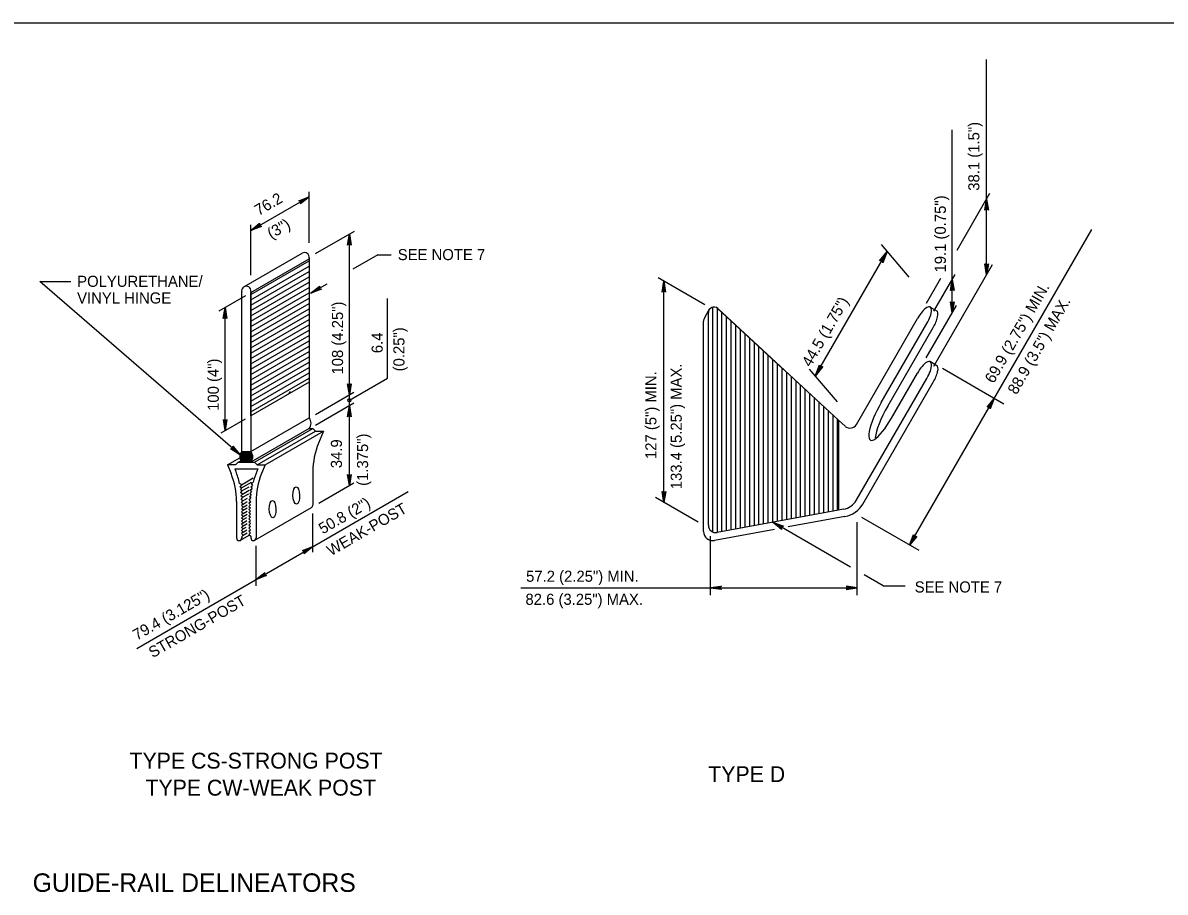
# Model space of a CAD drawing. Extents: x 640253 to 641999, y 298458 to 299646.
# Drawn here: x 640490.1 to 640798.8, y 298801.7 to 299036.6 of the extents above; entities that cross this region are included whole.
import ezdxf

# ---------------------------------------------------------------- set-up
doc = ezdxf.new("R2010")
doc.units = 0
doc.layers.add('1', color=7, linetype='Continuous')
doc.layers.add('2', color=7, linetype='Continuous')

msp = doc.modelspace()

# ---------------------------------------------------------------- linework, layer by layer
at = {"layer": '1'}
msp.add_line((640293.31, 299036.63), (641079.31, 299036.63), dxfattribs=at)
at = {"layer": '2'}
for p, q in [((640750.54, 298968.53), (640750.55, 299026.71)), ((640741.28, 298967.28), (640741.29, 299007.75)), ((640551.76, 298980.53), (640567.51, 298989.62)), ((640567.51, 298977.15), (640567.51, 298990.93)), ((640742.56, 298975.19), (640751.44, 298990.57)), ((640551.76, 298968.46), (640551.76, 298982)), ((640569.19, 298974.27), (640579.72, 298980.35)), ((640578.36, 298936.09), (640578.36, 298979.57)), ((640729.75, 298895.51), (640778.99, 298980.76)), ((640729.66, 298967.89), (640722.11, 298976.71)), ((640549.88, 298965.29), (640565.62, 298974.38)), ((640586.04, 298973.92), (640579.26, 298970.05)), ((640586.04, 298973.92), (640589.7, 298973.92)), ((640704.26, 298941.18), (640723.7, 298974.85)), ((640551.76, 298963.24), (640567.51, 298972.33)), ((640551.76, 298961.8), (640567.51, 298970.89)), ((640567.51, 298973.08), (640567.51, 298929.88)), ((640736.28, 298943.84), (640752.15, 298971.31)), ((640551.76, 298960.36), (640567.51, 298969.44)), ((640551.76, 298958.91), (640567.51, 298968)), ((640674.43, 298960.44), (640661.77, 298967.76)), ((640734.29, 298960.88), (640738.18, 298967.61)), ((640736.31, 298958.67), (640742.03, 298968.58)), ((640741.28, 298958.24), (640741.28, 298967.28)), ((640494.74, 298966.76), (640503.1, 298966.76)), ((640548.82, 298919.89), (640494.74, 298966.76)), ((640551.76, 298957.47), (640567.51, 298966.56)), ((640551.76, 298956.02), (640567.51, 298965.11)), ((640572.24, 298966.05), (640567.94, 298963.59)), ((640663.36, 298907.01), (640663.36, 298966.84)), ((640543.17, 298958.76), (640550.37, 298962.92)), ((640549.27, 298920.78), (640549.27, 298963.99)), ((640551.76, 298963.99), (640551.76, 298920.78)), ((640551.76, 298963.46), (640551.99, 298963.86)), ((640551.76, 298963.5), (640551.96, 298963.84)), ((640551.76, 298954.58), (640567.51, 298963.67)), ((640551.76, 298953.14), (640567.51, 298962.23)), ((640588.68, 298940.61), (640588.68, 298962.1)), ((640544.78, 298926.43), (640544.78, 298959.7)), ((640551.76, 298951.7), (640567.51, 298960.78)), ((640551.76, 298950.25), (640567.51, 298959.34)), ((640674.3, 298956.85), (640675.62, 298959.13)), ((640675.38, 298900.87), (640675.38, 298958.32)), ((640676.55, 298899.06), (640676.56, 298959.77)), ((640677.8, 298898.91), (640677.8, 298959.48)), ((640695.7, 298942.98), (640677.87, 298959.44)), ((640677.9, 298959.42), (640710.55, 298929.26)), ((640679.05, 298899.14), (640679.05, 298958.35)), ((640734.24, 298946.06), (640742.46, 298960.28)), ((640735.34, 298959.83), (640737.1, 298958.82)), ((640551.76, 298948.81), (640567.51, 298957.9)), ((640551.76, 298947.36), (640567.51, 298956.45)), ((640551.76, 298945.92), (640567.51, 298955.01)), ((640674.06, 298899.19), (640674.06, 298956.04)), ((640680.3, 298899.37), (640680.31, 298957.2)), ((640681.55, 298899.6), (640681.56, 298956.04)), ((640682.8, 298899.83), (640682.8, 298954.89)), ((640715.38, 298928.12), (640731.89, 298956.72)), ((640722.09, 298934.05), (640734.39, 298955.34)), ((640551.76, 298944.48), (640567.51, 298953.57)), ((640551.76, 298943.03), (640567.51, 298952.12)), ((640684.05, 298900.06), (640684.05, 298953.73)), ((640685.3, 298900.29), (640685.3, 298952.58)), ((640723.82, 298933.05), (640736.12, 298954.34)), ((640551.76, 298941.59), (640567.51, 298950.68)), ((640551.76, 298940.15), (640567.51, 298949.24)), ((640686.55, 298900.52), (640686.55, 298951.42)), ((640687.8, 298900.75), (640687.8, 298950.27)), ((640689.05, 298900.98), (640689.05, 298949.12)), ((640551.76, 298938.7), (640567.51, 298947.79)), ((640551.76, 298937.26), (640567.51, 298946.35)), ((640690.3, 298901.2), (640690.3, 298947.96)), ((640691.55, 298901.43), (640691.55, 298946.81)), ((640692.8, 298901.66), (640692.8, 298945.65)), ((640551.76, 298935.82), (640567.51, 298944.91)), ((640551.76, 298934.37), (640567.51, 298943.46)), ((640694.05, 298901.89), (640694.06, 298944.5)), ((640695.3, 298902.12), (640695.3, 298943.35)), ((640710.22, 298934.23), (640702.67, 298943.04)), ((640735.35, 298945.09), (640737.12, 298944.07)), ((640755.23, 298933.62), (640738.62, 298943.2)), ((640551.76, 298932.93), (640567.51, 298942.02)), ((640551.76, 298931.49), (640567.51, 298940.58)), ((640578.36, 298934.65), (640588.68, 298940.61)), ((640696.55, 298902.35), (640696.55, 298942.19)), ((640697.8, 298902.58), (640697.8, 298941.04)), ((640699.05, 298902.81), (640699.05, 298939.88)), ((640715.35, 298907.59), (640734.39, 298940.55)), ((640717.08, 298906.59), (640736.12, 298939.55)), ((640724.85, 298929.79), (640731.87, 298941.95)), ((640562.12, 298936.44), (640562.43, 298936.96)), ((640569.22, 298930.82), (640579.61, 298936.81)), ((640700.3, 298903.04), (640700.3, 298938.73)), ((640701.55, 298903.27), (640701.55, 298937.57)), ((640702.8, 298903.5), (640702.8, 298936.42)), ((640569.22, 298927.93), (640579.61, 298933.93)), ((640578.36, 298933.2), (640578.36, 298936.09)), ((640704.05, 298903.73), (640704.05, 298935.27)), ((640705.3, 298903.96), (640705.3, 298934.11)), ((640578.36, 298911.57), (640578.36, 298933.2)), ((640706.55, 298904.19), (640706.55, 298932.96)), ((640707.8, 298904.41), (640707.8, 298931.8)), ((640709.05, 298904.64), (640709.05, 298930.65)), ((640543.72, 298925.81), (640550.3, 298929.61)), ((640551.76, 298920.78), (640567.51, 298929.88)), ((640710.3, 298904.87), (640710.3, 298929.5)), ((640712.37, 298927.59), (640710.55, 298929.26)), ((640710.55, 298929.26), (640710.55, 298904.92)), ((640567.51, 298926.99), (640551.76, 298917.9)), ((640552.74, 298917.9), (640568.49, 298926.99)), ((640553.45, 298917.19), (640569.2, 298926.28)), ((640555.6, 298917.19), (640571.35, 298926.28)), ((640567.51, 298926.99), (640568.49, 298926.99)), ((640568.49, 298926.99), (640569.2, 298926.28)), ((640569.2, 298926.28), (640571.35, 298926.28)), ((640571.35, 298926.28), (640570.01, 298923.02)), ((640545.43, 298917.19), (640548.77, 298919.11)), ((640548.29, 298917.9), (640547.58, 298917.19)), ((640548.29, 298917.9), (640549, 298918.31)), ((640548.29, 298917.9), (640552.74, 298917.9)), ((640548.77, 298919.45), (640550.11, 298920.78)), ((640548.79, 298919.12), (640550.46, 298920.78)), ((640548.84, 298918.82), (640550.81, 298920.78)), ((640548.85, 298919.89), (640549.75, 298920.78)), ((640548.92, 298918.54), (640551.17, 298920.78)), ((640549.01, 298918.28), (640551.52, 298920.78)), ((640549.07, 298920.46), (640549.4, 298920.78)), ((640549.15, 298918.06), (640551.81, 298920.72)), ((640549.27, 298920.78), (640551.76, 298920.78)), ((640549.34, 298917.9), (640551.95, 298920.51)), ((640549.69, 298917.9), (640552.08, 298920.28)), ((640550.04, 298917.9), (640552.16, 298920.01)), ((640550.4, 298917.9), (640552.23, 298919.73)), ((640550.75, 298917.9), (640552.27, 298919.41)), ((640551.1, 298917.9), (640552.24, 298919.03)), ((640551.46, 298917.9), (640552.13, 298918.57)), ((640551.76, 298917.9), (640551.77, 298917.9)), ((640552.74, 298917.9), (640553.45, 298917.19)), ((640547.58, 298917.19), (640545.43, 298917.19)), ((640545.43, 298917.19), (640546.4, 298914.83)), ((640547.42, 298916.07), (640553.61, 298916.07)), ((640547.42, 298916.07), (640547.68, 298915.43)), ((640553.61, 298916.07), (640553.34, 298915.42)), ((640553.45, 298917.19), (640555.6, 298917.19)), ((640555.6, 298917.19), (640554.63, 298914.83)), ((640568.51, 298915.36), (640568.51, 298906.3)), ((640549.2, 298911.84), (640548.72, 298912.18)), ((640549.22, 298911.82), (640548.81, 298911.24)), ((640549.22, 298911.82), (640552.36, 298913.63)), ((640549.25, 298910.94), (640551.95, 298912.5)), ((640551.86, 298912.11), (640552.38, 298912.47)), ((640551.86, 298912.11), (640552.21, 298911.62)), ((640570.1, 298906.8), (640579.61, 298912.29)), ((640520.9, 298867.59), (640594.28, 298909.95)), ((640549.25, 298910.94), (640548.81, 298911.24)), ((640549.25, 298910.94), (640548.93, 298910.49)), ((640549.35, 298910.13), (640548.93, 298910.49)), ((640549.35, 298910.13), (640548.96, 298909.68)), ((640549.45, 298909.26), (640548.96, 298909.68)), ((640549.45, 298909.26), (640549.06, 298908.81)), ((640549.52, 298908.41), (640549.06, 298908.81)), ((640549.35, 298910.13), (640551.26, 298911.23)), ((640549.45, 298909.26), (640551.29, 298910.32)), ((640549.52, 298908.41), (640551.16, 298909.36)), ((640551.37, 298908.61), (640551.83, 298909.02)), ((640551.37, 298908.61), (640551.76, 298908.17)), ((640551.44, 298909.47), (640551.93, 298909.88)), ((640551.44, 298909.47), (640551.83, 298909.02)), ((640551.54, 298910.33), (640552.06, 298910.78)), ((640551.54, 298910.33), (640551.93, 298909.88)), ((640551.71, 298911.27), (640552.21, 298911.62)), ((640551.71, 298911.27), (640552.06, 298910.78)), ((640547.88, 298907.26), (640547.88, 298897.42)), ((640549.52, 298908.41), (640549.13, 298907.96)), ((640549.61, 298907.48), (640549.13, 298907.96)), ((640549.61, 298907.48), (640549.19, 298907.06)), ((640549.65, 298906.6), (640549.19, 298907.06)), ((640549.65, 298906.6), (640549.23, 298906.18)), ((640549.66, 298905.75), (640549.23, 298906.18)), ((640549.66, 298905.75), (640549.24, 298905.33)), ((640549.61, 298907.48), (640550.83, 298908.18)), ((640549.65, 298906.6), (640550.76, 298907.25)), ((640549.66, 298905.75), (640550.73, 298906.37)), ((640549.66, 298904.91), (640550.75, 298905.54)), ((640551.23, 298905.96), (640551.66, 298906.39)), ((640551.23, 298905.96), (640551.65, 298905.53)), ((640551.23, 298905.12), (640551.65, 298905.53)), ((640551.24, 298906.81), (640551.7, 298907.26)), ((640551.24, 298906.81), (640551.66, 298906.39)), ((640551.28, 298907.68), (640551.76, 298908.16)), ((640551.28, 298907.68), (640551.7, 298907.26)), ((640552.8, 298896.81), (640568.16, 298905.68)), ((640553.15, 298907.26), (640553.15, 298897.42)), ((640672.59, 298901.68), (640661.07, 298908.33)), ((640549.66, 298904.91), (640549.24, 298905.33)), ((640549.66, 298904.91), (640549.24, 298904.49)), ((640549.66, 298904.07), (640549.24, 298904.49)), ((640549.66, 298904.07), (640549.24, 298903.65)), ((640549.66, 298903.23), (640549.24, 298903.65)), ((640549.66, 298903.23), (640549.24, 298902.81)), ((640549.66, 298902.39), (640549.24, 298902.81)), ((640549.66, 298904.07), (640550.73, 298904.69)), ((640549.66, 298903.23), (640550.73, 298903.85)), ((640549.66, 298902.39), (640550.62, 298902.95)), ((640551.23, 298905.12), (640551.65, 298904.7)), ((640551.23, 298904.27), (640551.65, 298904.7)), ((640551.23, 298904.27), (640551.65, 298903.86)), ((640551.23, 298903.43), (640551.65, 298903.86)), ((640551.23, 298903.43), (640551.65, 298903.02)), ((640551.23, 298902.6), (640551.65, 298903.02)), ((640551.23, 298902.6), (640551.65, 298902.17)), ((640568.51, 298893.62), (640568.51, 298904.04)), ((640710.55, 298904.92), (640677.74, 298898.9)), ((640712.28, 298903.2), (640696.92, 298900.39)), ((640711.92, 298905.17), (640710.55, 298904.92)), ((640732.35, 298894.01), (640716.86, 298902.95)), ((640549.66, 298902.39), (640549.24, 298901.97)), ((640549.66, 298901.55), (640549.24, 298901.97)), ((640549.66, 298901.55), (640549.24, 298901.13)), ((640549.66, 298900.71), (640549.24, 298901.13)), ((640549.66, 298900.71), (640549.24, 298900.29)), ((640549.66, 298899.87), (640549.24, 298900.29)), ((640549.66, 298899.87), (640549.24, 298899.45)), ((640549.66, 298899.03), (640549.24, 298899.45)), ((640549.66, 298901.55), (640550.7, 298902.15)), ((640549.66, 298900.71), (640550.71, 298901.32)), ((640549.66, 298899.87), (640550.52, 298900.36)), ((640549.66, 298899.03), (640550.62, 298899.58)), ((640551.23, 298901.76), (640551.65, 298902.17)), ((640551.23, 298901.76), (640551.65, 298901.33)), ((640551.23, 298900.92), (640551.65, 298901.33)), ((640551.23, 298900.92), (640551.65, 298900.5)), ((640551.23, 298900.07), (640551.65, 298900.5)), ((640551.23, 298900.07), (640551.65, 298899.66)), ((640551.23, 298899.23), (640551.65, 298899.66)), ((640693.24, 298899.71), (640677.02, 298896.73)), ((640713.78, 298889.55), (640692.81, 298901.66)), ((640715.61, 298881.93), (640715.62, 298901.7)), ((640548.95, 298896.81), (640551.25, 298898.14)), ((640549.66, 298899.03), (640549.24, 298898.61)), ((640549.66, 298898.19), (640549.24, 298898.61)), ((640549.3, 298897.83), (640549.66, 298898.19)), ((640549.3, 298897.83), (640549.3, 298897.42)), ((640549.66, 298898.19), (640550.71, 298898.8)), ((640551.23, 298899.23), (640551.65, 298898.82)), ((640551.23, 298898.4), (640551.65, 298898.82)), ((640551.23, 298898.4), (640551.73, 298897.89)), ((640551.73, 298897.89), (640551.73, 298897.42)), ((640675.94, 298881.93), (640675.94, 298897.93)), ((640553.15, 298884.45), (640553.15, 298895.29)), ((640722.62, 298884.45), (640717.48, 298887.42)), ((640624.71, 298883.95), (640715.61, 298883.95)), ((640722.62, 298884.45), (640728.59, 298884.45))]:
    msp.add_line(p, q, dxfattribs=at)
for points in [[(640564.86, 298988.51), (640565.05, 298988.38), (640567.51, 298989.62), (640564.86, 298988.51), (640564.67, 298988.54), (640567.51, 298989.62), (640565.2, 298988.13), (640565.21, 298987.91), (640567.51, 298989.62), (640565.15, 298987.71), (640565.21, 298987.91)], [(640750.18, 298986.16), (640750.39, 298986.27), (640750.54, 298989.02), (640750.18, 298986.16), (640750.06, 298986.02), (640750.54, 298989.02), (640750.68, 298986.27), (640750.88, 298986.17), (640750.54, 298989.02), (640751.02, 298986.02), (640750.88, 298986.17)], [(640554.41, 298981.65), (640554.22, 298981.78), (640551.76, 298980.53), (640554.41, 298981.65), (640554.6, 298981.62), (640551.76, 298980.53), (640554.07, 298982.02), (640554.06, 298982.25), (640551.76, 298980.53), (640554.12, 298982.45), (640554.06, 298982.25)], [(640578, 298976.71), (640578.21, 298976.82), (640578.36, 298979.57), (640578, 298976.71), (640577.87, 298976.57), (640578.36, 298979.57), (640578.49, 298976.82), (640578.7, 298976.72), (640578.36, 298979.57), (640578.83, 298976.57), (640578.7, 298976.72)], [(640721.82, 298972.37), (640722.07, 298972.35), (640723.7, 298974.85), (640721.82, 298972.37), (640721.63, 298972.3), (640723.7, 298974.85), (640722.34, 298972.2), (640722.48, 298972), (640723.7, 298974.85), (640722.53, 298971.78), (640722.48, 298972)], [(640750.9, 298971.38), (640750.69, 298971.27), (640750.54, 298968.53), (640750.9, 298971.38), (640751.02, 298971.53), (640750.54, 298968.53), (640750.4, 298971.27), (640750.2, 298971.37), (640750.54, 298968.53), (640750.06, 298971.53), (640750.2, 298971.37)], [(640740.92, 298964.43), (640741.13, 298964.53), (640741.28, 298967.28), (640740.92, 298964.43), (640740.8, 298964.28), (640741.28, 298967.28), (640741.42, 298964.53), (640741.62, 298964.43), (640741.28, 298967.28), (640741.76, 298964.28), (640741.62, 298964.43)], [(640570.6, 298964.7), (640570.4, 298964.82), (640567.94, 298963.59), (640570.6, 298964.7), (640570.79, 298964.66), (640567.94, 298963.59), (640570.26, 298965.07), (640570.25, 298965.3), (640567.94, 298963.59), (640570.31, 298965.49), (640570.25, 298965.3)], [(640663, 298963.99), (640663.21, 298964.09), (640663.36, 298966.84), (640663, 298963.99), (640662.88, 298963.84), (640663.36, 298966.84), (640663.49, 298964.1), (640663.7, 298963.99), (640663.36, 298966.84), (640663.83, 298963.84), (640663.7, 298963.99)], [(640741.64, 298961.1), (640741.43, 298960.99), (640741.28, 298958.24), (640741.64, 298961.1), (640741.76, 298961.24), (640741.28, 298958.24), (640741.15, 298960.99), (640740.94, 298961.09), (640741.28, 298958.24), (640740.81, 298961.24), (640740.94, 298961.09)], [(640544.43, 298956.84), (640544.63, 298956.95), (640544.78, 298959.7), (640544.43, 298956.84), (640544.3, 298956.7), (640544.78, 298959.7), (640544.92, 298956.95), (640545.12, 298956.85), (640544.78, 298959.7), (640545.26, 298956.7), (640545.12, 298956.85)], [(640706.14, 298943.66), (640705.89, 298943.67), (640704.26, 298941.18), (640706.14, 298943.66), (640706.34, 298943.73), (640704.26, 298941.18), (640705.62, 298943.83), (640705.48, 298944.03), (640704.26, 298941.18), (640705.44, 298944.25), (640705.48, 298944.03)], [(640706.14, 298943.66), (640705.89, 298943.67), (640704.26, 298941.18), (640706.14, 298943.66), (640706.34, 298943.73), (640704.26, 298941.18), (640705.62, 298943.83), (640705.48, 298944.03), (640704.26, 298941.18), (640705.44, 298944.25), (640705.48, 298944.03)], [(640578.72, 298938.95), (640578.51, 298938.84), (640578.36, 298936.09), (640578.72, 298938.95), (640578.84, 298939.09), (640578.36, 298936.09), (640578.22, 298938.84), (640578.02, 298938.94), (640578.36, 298936.09), (640577.88, 298939.09), (640578.02, 298938.94)], [(640750.89, 298932.82), (640751.12, 298932.81), (640752.63, 298935.12), (640750.89, 298932.82), (640750.71, 298932.76), (640752.63, 298935.12), (640751.37, 298932.67), (640751.5, 298932.48), (640752.63, 298935.12), (640751.54, 298932.28), (640751.5, 298932.48)], [(640578, 298930.35), (640578.21, 298930.46), (640578.36, 298933.2), (640578, 298930.35), (640577.87, 298930.2), (640578.36, 298933.2), (640578.49, 298930.46), (640578.7, 298930.36), (640578.36, 298933.2), (640578.83, 298930.2), (640578.7, 298930.36)], [(640545.14, 298929.28), (640544.94, 298929.18), (640544.78, 298926.43), (640545.14, 298929.28), (640545.27, 298929.43), (640544.78, 298926.43), (640544.65, 298929.17), (640544.45, 298929.27), (640544.78, 298926.43), (640544.31, 298929.43), (640544.45, 298929.27)], [(640546.93, 298922.05), (640546.87, 298921.83), (640548.82, 298919.89), (640546.93, 298922.05), (640546.9, 298922.25), (640548.82, 298919.89), (640546.68, 298921.61), (640546.47, 298921.53), (640548.82, 298919.89), (640546.26, 298921.53), (640546.47, 298921.53)], [(640578.72, 298914.42), (640578.51, 298914.32), (640578.36, 298911.57), (640578.72, 298914.42), (640578.84, 298914.57), (640578.36, 298911.57), (640578.22, 298914.31), (640578.02, 298914.41), (640578.36, 298911.57), (640577.88, 298914.57), (640578.02, 298914.41)], [(640663.72, 298909.86), (640663.51, 298909.75), (640663.36, 298907.01), (640663.72, 298909.86), (640663.84, 298910.01), (640663.36, 298907.01), (640663.22, 298909.75), (640663.02, 298909.85), (640663.36, 298907.01), (640662.88, 298910.01), (640663.02, 298909.85)], [(640695.1, 298899.93), (640695.11, 298900.16), (640692.81, 298901.66), (640695.1, 298899.93), (640695.16, 298899.75), (640692.81, 298901.66), (640695.25, 298900.41), (640695.44, 298900.54), (640692.81, 298901.66), (640695.64, 298900.58), (640695.44, 298900.54)], [(640731.49, 298897.8), (640731.26, 298897.81), (640729.75, 298895.51), (640731.49, 298897.8), (640731.67, 298897.86), (640729.75, 298895.51), (640731.01, 298897.95), (640730.88, 298898.14), (640729.75, 298895.51), (640730.84, 298898.34), (640730.88, 298898.14)], [(640565.86, 298893.96), (640566.06, 298893.83), (640568.51, 298895.07), (640565.86, 298893.96), (640565.67, 298893.99), (640568.51, 298895.07), (640566.2, 298893.58), (640566.22, 298893.36), (640568.51, 298895.07), (640566.15, 298893.16), (640566.22, 298893.36)], [(640555.8, 298887.32), (640555.6, 298887.45), (640553.15, 298886.21), (640555.8, 298887.32), (640555.99, 298887.29), (640553.15, 298886.21), (640555.46, 298887.7), (640555.44, 298887.92), (640553.15, 298886.21), (640555.51, 298888.12), (640555.44, 298887.92)], [(640678.79, 298883.6), (640678.68, 298883.8), (640675.94, 298883.95), (640678.79, 298883.6), (640678.94, 298883.47), (640675.94, 298883.95), (640678.68, 298884.09), (640678.78, 298884.29), (640675.94, 298883.95), (640678.94, 298884.43), (640678.78, 298884.29)], [(640712.76, 298883.6), (640712.87, 298883.8), (640715.61, 298883.95), (640712.76, 298883.6), (640712.61, 298883.47), (640715.61, 298883.95), (640712.87, 298884.09), (640712.77, 298884.29), (640715.61, 298883.95), (640712.61, 298884.43), (640712.77, 298884.29)]]:
    msp.add_lwpolyline(points, dxfattribs=at)
msp.add_lwpolyline([(640551.76, 298930.46), (640551.76, 298963.72), (640567.51, 298972.81), (640567.51, 298939.55)], close=True, dxfattribs=at)
msp.add_circle((640578.36, 298934.65), 0.444, dxfattribs=at)
for centre, radius, start, end in [((640566.26, 298973.28), 1.26, 350.9133, 119.9792), ((640550.51, 298964.19), 1.26, 350.9133, 189.0867), ((640676.88, 298958.32), 1.5, 47.2827, 180.0033), ((640675.56, 298956.04), 1.5, 147.1819, 180.0033), ((640565.73, 298928.43), 2.29, 320.9923, 39.0623), ((640713.65, 298929.12), 2, 230.2615, 329.996), ((640588.76, 298915.36), 20.25, 157.7877, 180), ((640551.05, 298919.34), 2.29, 140.9377, 219.0623), ((640549.98, 298919.34), 2.29, 320.9923, 39.0623), ((640527.88, 298907.26), 20, 0, 22.2204), ((640527.55, 298907.2), 21.75, 13.2354, 22.2267), ((640573.48, 298907.2), 21.75, 157.7963, 165.9872), ((640573.15, 298907.26), 20, 157.7833, 180), ((640567.8, 298906.3), 0.709, 300.0103, 0), ((640711.02, 298910.09), 5, 280.3803, 329.996), ((640711.02, 298910.09), 7, 280.3899, 329.996), ((640677.38, 298900.87), 2, 180.0098, 280.3902), ((640548.59, 298897.42), 0.709, 180, 0), ((640552.44, 298897.42), 0.709, 180.005, 0), ((640676.56, 298899.19), 2.5, 179.9993, 280.3971)]:
    msp.add_arc(centre, radius, start, end, dxfattribs=at)
for centre, major_axis, ratio, start_param, end_param in [((640733.31, 298956.32), (2.03, 3.52), 0.351581, 4.636261, 7.943286), ((640735.04, 298955.32), (2.03, 3.52), 0.351581, 4.636261, 6.257684), ((640733.3, 298941.54), (2.05, 3.55), 0.351581, 4.636261, 7.943286), ((640735.03, 298940.54), (2.05, 3.55), 0.351581, 4.636261, 6.250381), ((640723.43, 298931.84), (4.28, 7.98), 0.247592, 1.425353, 4.587399), ((640725.16, 298930.84), (4.28, 7.98), 0.247592, 1.425353, 2.620687)]:
    msp.add_ellipse(centre, major_axis=major_axis, ratio=ratio, start_param=start_param, end_param=end_param, dxfattribs=at)
for centre in [(640564.02, 298908.91), (640557.63, 298905.22)]:
    msp.add_ellipse(centre, major_axis=(0.05, -2.36), ratio=0.379302, dxfattribs=at)

# ---------------------------------------------------------------- texts
for s, rotation, p in [('38.1 (1.5") ', 89.996, (640748.6, 298991.25)), ('76.2', 30, (640553.85, 298984.42)), ('19.1 (0.75") ', 89.996, (640739.54, 298969.16)), ('(3")', 30, (640557.26, 298978.14)), ('69.9 (2.75") MIN.', 59.996, (640752.47, 298938.98)), ('108 (4.25")', 90, (640576.66, 298941.59)), ('44.5 (1.75") ', 59.996, (640703.01, 298943.41)), ('88.9 (3.5") MAX.', 59.996, (640758.63, 298935.94)), ('6.4 ', 90, (640587.37, 298947.36)), ('(0.25")', 90, (640593.25, 298942.44)), ('100 (4")', 90, (640543.08, 298931.76)), ('133.4 (5.25") MAX.', 89.996, (640668.18, 298910.59)), ('127 (5") MIN.', 89.996, (640661.33, 298918.76)), ('(1.375")', 90, (640583.43, 298911.5)), ('34.9', 90, (640576.36, 298916.27)), ('50.8 (2")', 30, (640571.17, 298898.36)), ('WEAK-POST', 30, (640573.38, 298892.44)), ('79.4 (3.125")', 30, (640520.96, 298869.66)), ('STRONG-POST', 30, (640525.22, 298864.91))]:
    msp.add_text(s, height=3, rotation=rotation, dxfattribs=at).set_placement(p)
for s, height, p in [('SEE NOTE 7', 3, (640591.44, 298972.5)), ('POLYURETHANE/', 3, (640504.82, 298965.28)), ('VINYL HINGE  ', 3, (640504.8, 298960.78)), ('57.2 (2.25") MIN.', 3, (640626.12, 298885.58)), ('SEE NOTE 7', 3, (640731.13, 298882.68)), ('82.6 (3.25") MAX.', 3, (640625.95, 298879.35)), ('TYPE CS-STRONG POST', 4.3, (640518.97, 298835.09)), ('TYPE D', 4.3, (640675.35, 298831.44)), ('TYPE CW-WEAK POST', 4.3, (640523.27, 298827.79)), ('GUIDE-RAIL DELINEATORS', 5, (640492.79, 298801.78))]:
    msp.add_text(s, height=height, dxfattribs=at).set_placement(p)

doc.saveas('drawing.dxf')
